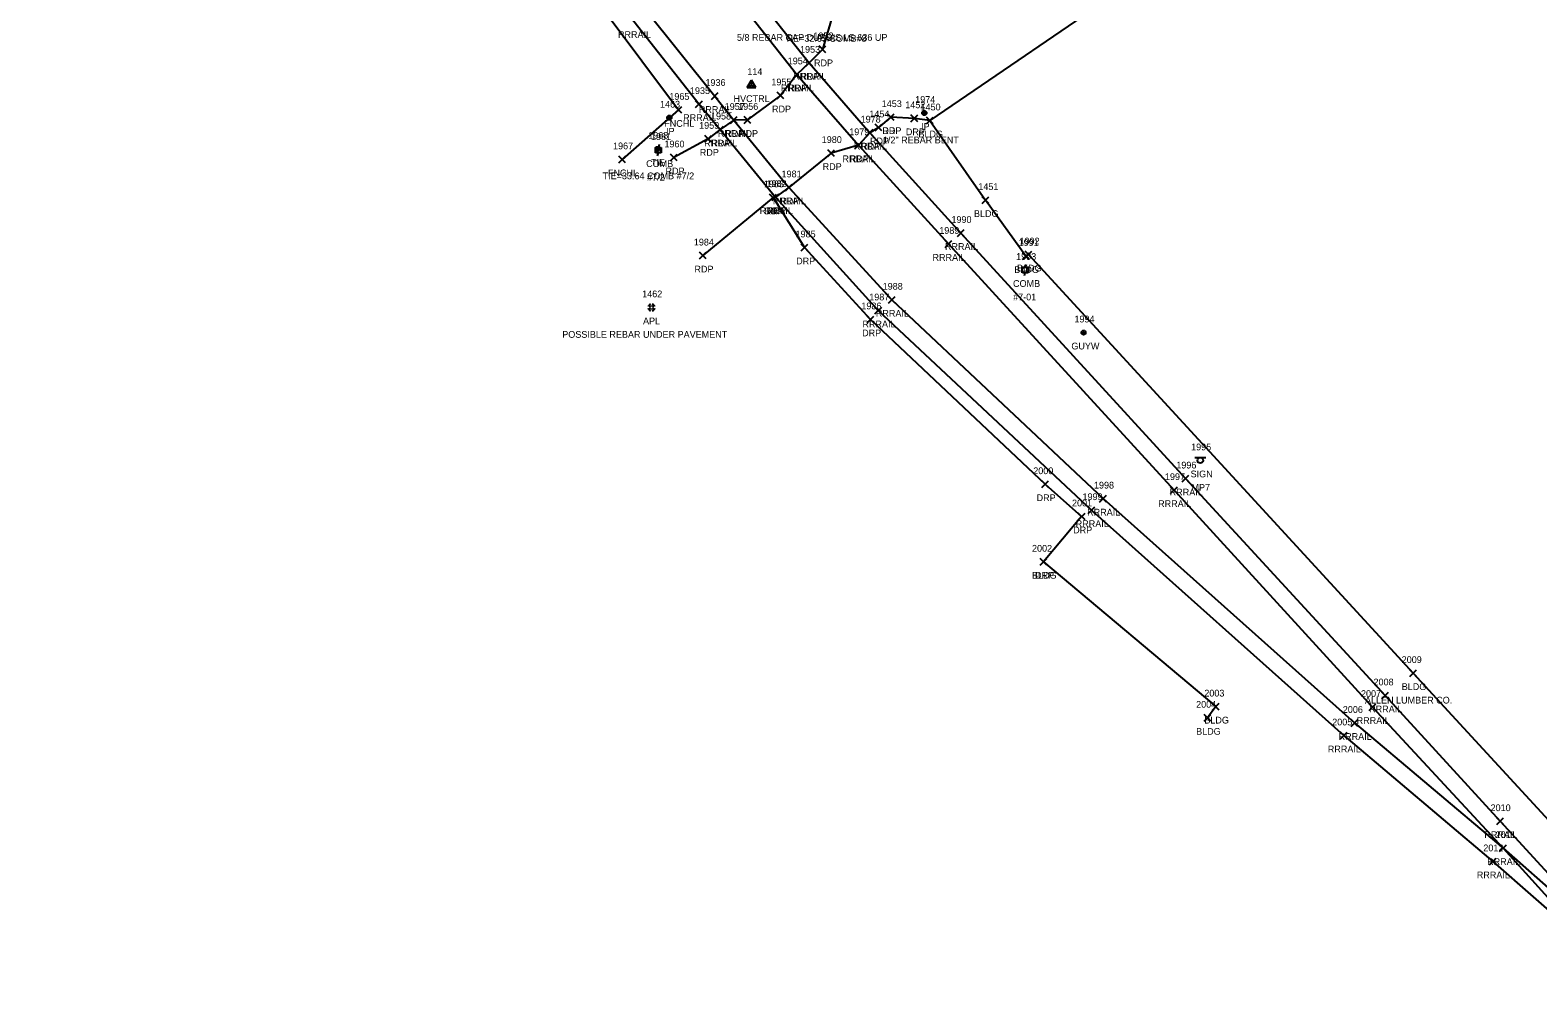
# Model space of a CAD drawing. Extents: x 1635588 to 1637550, y 621583 to 623638.
# Drawn here: x 1636590.6 to 1637037.4, y 621876.2 to 622165 of the extents above; entities that cross this region are included whole.
import ezdxf

# ---------------------------------------------------------------- set-up
doc = ezdxf.new("R2010")
doc.units = 0
for name, color, linetype in [('C_A', 7, 'Continuous'), ('C_C', 7, 'Continuous'), ('C_I', 7, 'Continuous'), ('CBP', 7, 'Continuous'), ('CPSM', 7, 'Continuous'), ('Default', 7, 'Continuous'), ('L_A', 7, 'Continuous'), ('L_C', 7, 'Continuous'), ('L_I', 7, 'Continuous'), ('L_TIC', 7, 'Continuous'), ('LBC', 7, 'Continuous'), ('LFNC', 7, 'Continuous'), ('M_A', 7, 'Continuous'), ('M_C', 7, 'Continuous'), ('M_I', 7, 'Continuous'), ('MPIR', 7, 'Continuous'), ('P_A', 7, 'Continuous'), ('P_I', 7, 'Continuous'), ('P_TIC', 7, 'Continuous'), ('PET', 7, 'Continuous'), ('R_A', 7, 'Continuous'), ('R_I', 7, 'Continuous'), ('R_TIC', 7, 'Continuous'), ('RDP', 7, 'Continuous'), ('RR', 7, 'Continuous'), ('S_A', 7, 'Continuous'), ('S_C', 7, 'Continuous'), ('S_I', 7, 'Continuous'), ('SSGN', 7, 'Continuous'), ('U_A', 7, 'Continuous'), ('U_C', 7, 'Continuous'), ('U_I', 7, 'Continuous'), ('UP', 7, 'Continuous'), ('UPGW', 7, 'Continuous')]:
    doc.layers.add(name, color=color, linetype=linetype)

msp = doc.modelspace()

# ---------------------------------------------------------------- linework, layer by layer
at = {"layer": 'CBP'}
for radius in [0.625, 0.0833]:
    msp.add_circle((1636776.52, 622129.85), radius, dxfattribs=at)
at = {"layer": 'CPSM'}
for p, q in [((1636803.12, 622148), (1636804.37, 622150.17)), ((1636805.62, 622148), (1636804.37, 622150.17)), ((1636804.37, 622148.73), (1636804.37, 622150.17)), ((1636803.12, 622148), (1636804.37, 622148.73)), ((1636803.12, 622148), (1636805.62, 622148)), ((1636804.37, 622148.73), (1636804.37, 622148.73)), ((1636804.37, 622148.73), (1636805.62, 622148))]:
    msp.add_line(p, q, dxfattribs=at)
at = {"layer": 'Default'}
for p, q in [((1636774.09, 622083.5), (1636774.45, 622083.15)), ((1636774.09, 622082.23), (1636774.45, 622082.58)), ((1636774.13, 622082.87), (1636774.43, 622082.87)), ((1636774.73, 622083.17), (1636774.73, 622083.47)), ((1636774.73, 622082.27), (1636774.73, 622082.57)), ((1636775.01, 622083.15), (1636775.37, 622083.5)), ((1636775.01, 622082.58), (1636775.37, 622082.23)), ((1636775.03, 622082.87), (1636775.33, 622082.87))]:
    msp.add_line(p, q, dxfattribs=at)
for start, end in [(105, 165), (195, 255), (15, 75), (285, 345)]:
    msp.add_arc((1636774.73, 622082.87), 1, start, end, dxfattribs=at)
at = {"layer": 'L_TIC'}
for points in [[(1636781.77, 622140.38), (1636783.77, 622142.38)], [(1636783.77, 622140.38), (1636781.77, 622142.38)], [(1636856.25, 622137.25), (1636858.25, 622139.25)], [(1636858.25, 622137.25), (1636856.25, 622139.25)], [(1636765.09, 622125.73), (1636767.09, 622127.73)], [(1636767.09, 622125.73), (1636765.09, 622127.73)], [(1636872.71, 622113.67), (1636874.71, 622115.67)], [(1636874.71, 622113.67), (1636872.71, 622115.67)], [(1636884.66, 622097.09), (1636886.66, 622099.09)], [(1636886.66, 622097.09), (1636884.66, 622099.09)], [(1636885.49, 622097.53), (1636887.49, 622099.53)], [(1636887.49, 622097.53), (1636885.49, 622099.53)], [(1636889.91, 622006.5), (1636891.91, 622008.5)], [(1636891.91, 622006.5), (1636889.91, 622008.5)], [(1636999.47, 621973.51), (1637001.47, 621975.51)], [(1637001.47, 621973.51), (1636999.47, 621975.51)], [(1636938.54, 621960.26), (1636940.54, 621962.26)], [(1636940.54, 621960.26), (1636938.54, 621962.26)], [(1636940.98, 621963.59), (1636942.98, 621965.59)], [(1636942.98, 621963.59), (1636940.98, 621965.59)]]:
    msp.add_lwpolyline(points, dxfattribs=at)
at = {"layer": 'LBC'}
for points in [[(1636917.78, 622179.59), (1636857.25, 622138.25), (1636873.71, 622114.67)], [(1636885.66, 622098.09), (1636873.71, 622114.67)], [(1636885.66, 622098.09), (1636886.49, 622098.53), (1637000.47, 621974.51), (1637086.58, 621881), (1637094.62, 621887.96), (1637096.59, 621890.08)], [(1636890.91, 622007.5), (1636941.98, 621964.59), (1636939.54, 621961.26)]]:
    msp.add_lwpolyline(points, dxfattribs=at)
at = {"layer": 'LFNC'}
msp.add_lwpolyline([(1636739.42, 622178.03), (1636750.15, 622185.05), (1636782.77, 622141.38), (1636766.09, 622126.73)], dxfattribs=at)
at = {"layer": 'MPIR'}
for points in [[(1636855.58, 622140.82), (1636855.3, 622140.32), (1636855.87, 622140.32)], [(1636780.01, 622139.41), (1636779.72, 622138.91), (1636780.3, 622138.91)]]:
    msp.add_lwpolyline(points, close=True, dxfattribs=at)
for centre in [(1636855.58, 622140.48), (1636780.01, 622139.08)]:
    msp.add_circle(centre, 0.667, dxfattribs=at)
at = {"layer": 'P_TIC'}
for points in [[(1636824.41, 622158.33), (1636826.41, 622160.33)], [(1636826.41, 622158.33), (1636824.41, 622160.33)], [(1636820.45, 622154.32), (1636822.45, 622156.32)], [(1636822.45, 622154.32), (1636820.45, 622156.32)], [(1636816.8, 622150.9), (1636818.8, 622152.9)], [(1636818.8, 622150.9), (1636816.8, 622152.9)], [(1636811.96, 622144.66), (1636813.96, 622146.66)], [(1636813.96, 622144.66), (1636811.96, 622146.66)], [(1636794.06, 622134.55), (1636796.06, 622136.55)], [(1636796.06, 622134.55), (1636794.06, 622136.55)], [(1636798.12, 622137.4), (1636800.12, 622139.4)], [(1636800.12, 622137.4), (1636798.12, 622139.4)], [(1636802.18, 622137.41), (1636804.18, 622139.41)], [(1636804.18, 622137.41), (1636802.18, 622139.41)], [(1636840.98, 622135.18), (1636842.98, 622137.18)], [(1636842.98, 622135.18), (1636840.98, 622137.18)], [(1636844.66, 622138.23), (1636846.66, 622140.23)], [(1636846.66, 622138.23), (1636844.66, 622140.23)], [(1636790.56, 622131.8), (1636792.56, 622133.8)], [(1636792.56, 622131.8), (1636790.56, 622133.8)], [(1636835.04, 622129.9), (1636837.04, 622131.9)], [(1636837.04, 622129.9), (1636835.04, 622131.9)], [(1636838.4, 622133.64), (1636840.4, 622135.64)], [(1636840.4, 622133.64), (1636838.4, 622135.64)], [(1636780.4, 622126.29), (1636782.4, 622128.29)], [(1636782.4, 622126.29), (1636780.4, 622128.29)], [(1636826.97, 622127.6), (1636828.97, 622129.6)], [(1636828.97, 622127.6), (1636826.97, 622129.6)], [(1636814.41, 622117.42), (1636816.41, 622119.42)], [(1636816.41, 622117.42), (1636814.41, 622119.42)], [(1636809.75, 622114.47), (1636811.75, 622116.47)], [(1636811.75, 622114.47), (1636809.75, 622116.47)], [(1636810.52, 622114.54), (1636812.52, 622116.54)], [(1636812.52, 622114.54), (1636810.52, 622116.54)], [(1636788.98, 622097.22), (1636790.98, 622099.22)], [(1636790.98, 622097.22), (1636788.98, 622099.22)]]:
    msp.add_lwpolyline(points, dxfattribs=at)
at = {"layer": 'PET'}
for points in [[(1636828.72, 622170.37), (1636825.41, 622159.33)], [(1636825.41, 622159.33), (1636821.45, 622155.32), (1636817.8, 622151.9), (1636812.96, 622145.66), (1636803.18, 622138.41), (1636799.12, 622138.4), (1636795.06, 622135.55), (1636791.56, 622132.8), (1636781.4, 622127.29)], [(1636841.98, 622136.18), (1636839.4, 622134.64)], [(1636845.66, 622139.23), (1636841.98, 622136.18)], [(1636839.4, 622134.64), (1636836.04, 622130.9), (1636827.97, 622128.6), (1636815.41, 622118.42), (1636811.52, 622115.54), (1636810.75, 622115.47), (1636789.98, 622098.22)]]:
    msp.add_lwpolyline(points, dxfattribs=at)
at = {"layer": 'R_TIC'}
for points in [[(1636820.45, 622154.32), (1636822.45, 622156.32)], [(1636822.45, 622154.32), (1636820.45, 622156.32)], [(1636816.8, 622150.9), (1636818.8, 622152.9)], [(1636818.8, 622150.9), (1636816.8, 622152.9)], [(1636792.48, 622144.5), (1636794.48, 622146.5)], [(1636794.48, 622144.5), (1636792.48, 622146.5)], [(1636787.83, 622142.09), (1636789.83, 622144.09)], [(1636789.83, 622142.09), (1636787.83, 622144.09)], [(1636794.06, 622134.55), (1636796.06, 622136.55)], [(1636796.06, 622134.55), (1636794.06, 622136.55)], [(1636798.12, 622137.4), (1636800.12, 622139.4)], [(1636800.12, 622137.4), (1636798.12, 622139.4)], [(1636844.66, 622138.23), (1636846.66, 622140.23)], [(1636846.66, 622138.23), (1636844.66, 622140.23)], [(1636851.64, 622137.89), (1636853.64, 622139.89)], [(1636853.64, 622137.89), (1636851.64, 622139.89)], [(1636835.04, 622129.9), (1636837.04, 622131.9)], [(1636837.04, 622129.9), (1636835.04, 622131.9)], [(1636838.4, 622133.64), (1636840.4, 622135.64)], [(1636840.4, 622133.64), (1636838.4, 622135.64)], [(1636814.41, 622117.42), (1636816.41, 622119.42)], [(1636816.41, 622117.42), (1636814.41, 622119.42)], [(1636809.75, 622114.47), (1636811.75, 622116.47)], [(1636811.75, 622114.47), (1636809.75, 622116.47)], [(1636810.52, 622114.54), (1636812.52, 622116.54)], [(1636812.52, 622114.54), (1636810.52, 622116.54)], [(1636865.41, 622103.91), (1636867.41, 622105.91)], [(1636867.41, 622103.91), (1636865.41, 622105.91)], [(1636819.12, 622099.62), (1636821.12, 622101.62)], [(1636821.12, 622099.62), (1636819.12, 622101.62)], [(1636861.72, 622100.67), (1636863.72, 622102.67)], [(1636863.72, 622100.67), (1636861.72, 622102.67)], [(1636840.96, 622080.95), (1636842.96, 622082.95)], [(1636842.96, 622080.95), (1636840.96, 622082.95)], [(1636844.94, 622084.12), (1636846.94, 622086.12)], [(1636846.94, 622084.12), (1636844.94, 622086.12)], [(1636838.67, 622078.31), (1636840.67, 622080.31)], [(1636840.67, 622078.31), (1636838.67, 622080.31)], [(1636890.38, 622029.47), (1636892.38, 622031.47)], [(1636892.38, 622029.47), (1636890.38, 622031.47)], [(1636928.58, 622027.72), (1636930.58, 622029.72)], [(1636930.58, 622027.72), (1636928.58, 622029.72)], [(1636932.01, 622031.15), (1636934.01, 622033.15)], [(1636934.01, 622031.15), (1636932.01, 622033.15)], [(1636907.55, 622025.21), (1636909.55, 622027.21)], [(1636909.55, 622025.21), (1636907.55, 622027.21)], [(1636901.21, 622019.92), (1636903.21, 622021.92)], [(1636903.21, 622019.92), (1636901.21, 622021.92)], [(1636904.16, 622021.78), (1636906.16, 622023.78)], [(1636906.16, 622021.78), (1636904.16, 622023.78)], [(1636889.91, 622006.5), (1636891.91, 622008.5)], [(1636891.91, 622006.5), (1636889.91, 622008.5)], [(1636991.12, 621966.88), (1636993.12, 621968.88)], [(1636993.12, 621966.88), (1636991.12, 621968.88)], [(1636987.41, 621963.46), (1636989.41, 621965.46)], [(1636989.41, 621963.46), (1636987.41, 621965.46)], [(1636982.07, 621958.74), (1636984.07, 621960.74)], [(1636984.07, 621958.74), (1636982.07, 621960.74)], [(1636978.87, 621955.02), (1636980.87, 621957.02)], [(1636980.87, 621955.02), (1636978.87, 621957.02)], [(1637025.25, 621929.62), (1637027.25, 621931.62)], [(1637027.25, 621929.62), (1637025.25, 621931.62)], [(1637026.08, 621921.66), (1637028.08, 621923.66)], [(1637028.08, 621921.66), (1637026.08, 621923.66)], [(1637026.08, 621921.66), (1637028.08, 621923.66)], [(1637028.08, 621921.66), (1637026.08, 621923.66)], [(1637023.02, 621917.73), (1637025.02, 621919.73)], [(1637025.02, 621917.73), (1637023.02, 621919.73)]]:
    msp.add_lwpolyline(points, dxfattribs=at)
at = {"layer": 'RDP'}
for points in [[(1636852.64, 622138.89), (1636845.66, 622139.23)], [(1636857.25, 622138.25), (1636852.64, 622138.89)], [(1636810.75, 622115.47), (1636820.12, 622100.62), (1636839.67, 622079.31), (1636891.38, 622030.47), (1636902.21, 622020.92), (1636890.91, 622007.5)]]:
    msp.add_lwpolyline(points, dxfattribs=at)
at = {"layer": 'RR'}
for points in [[(1636590.62, 622643.06), (1636603.96, 622594.72), (1636620.27, 622536.36), (1636632.07, 622498.45), (1636643.29, 622466.78), (1636655.39, 622436.56), (1636668.93, 622406.09), (1636689.56, 622363.97), (1636710.33, 622322.06), (1636729.55, 622284.99), (1636743.57, 622259.26), (1636761.55, 622228.91), (1636778.55, 622203.2), (1636800.49, 622173.78), (1636817.8, 622151.9), (1636836.04, 622130.9), (1636862.72, 622101.67), (1636929.58, 622028.72), (1636988.41, 621964.46), (1637027.08, 621922.66), (1637047.82, 621899.75)], [(1636595.36, 622644.51), (1636608.64, 622596.11), (1636625.13, 622537.69), (1636636.8, 622500.24), (1636648.02, 622468.59), (1636659.97, 622438.55), (1636673.52, 622408.34), (1636693.85, 622366.08), (1636714.7, 622324.39), (1636733.88, 622287.48), (1636747.97, 622261.4), (1636765.42, 622232.02), (1636782.99, 622205.69), (1636804, 622177.32), (1636821.45, 622155.32), (1636839.4, 622134.64), (1636866.41, 622104.91), (1636933.01, 622032.15), (1636992.12, 621967.88), (1637026.25, 621930.62), (1637051.37, 621903.17)], [(1636647.57, 622303.46), (1636681.53, 622274.07), (1636698.35, 622258.6), (1636736.07, 622216.66), (1636772.81, 622171.31), (1636793.48, 622145.5), (1636799.12, 622138.4), (1636815.41, 622118.42), (1636845.94, 622085.12), (1636908.55, 622026.21), (1636983.07, 621959.74), (1637027.08, 621922.66), (1637050.39, 621902.14), (1637074.4, 621880.01)], [(1636645.23, 622298.69), (1636678.25, 622270.68), (1636695.49, 622253.83), (1636732.46, 622213.3), (1636769.51, 622167.71), (1636788.83, 622143.09), (1636795.06, 622135.55), (1636811.52, 622115.54), (1636841.96, 622081.95), (1636905.16, 622022.78), (1636979.87, 621956.02), (1637024.02, 621918.73), (1637048, 621897.73), (1637071.19, 621876.23)]]:
    msp.add_lwpolyline(points, dxfattribs=at)
at = {"layer": 'SSGN'}
for p, q in [((1636935.71, 622038.38), (1636939.05, 622038.38)), ((1636937.36, 622037.55), (1636937.36, 622037.55))]:
    msp.add_line(p, q, dxfattribs=at)
msp.add_circle((1636937.36, 622037.55), 0.833, dxfattribs=at)
at = {"layer": 'UP'}
for p, q in [((1636775.94, 622128.63), (1636775.94, 622130.29)), ((1636775.94, 622130.29), (1636777.61, 622130.29)), ((1636777.61, 622128.63), (1636775.94, 622128.63)), ((1636776.53, 622127.79), (1636776.78, 622128.63)), ((1636777.03, 622131.13), (1636776.78, 622130.29)), ((1636776.78, 622129.46), (1636776.78, 622129.46)), ((1636777.61, 622130.29), (1636777.61, 622128.63)), ((1636884.66, 622093.12), (1636884.66, 622094.79)), ((1636884.66, 622094.79), (1636886.33, 622094.79)), ((1636886.33, 622093.12), (1636884.66, 622093.12)), ((1636885.25, 622092.29), (1636885.5, 622093.12)), ((1636885.75, 622095.62), (1636885.5, 622094.79)), ((1636885.5, 622093.95), (1636885.5, 622093.95)), ((1636886.33, 622094.79), (1636886.33, 622093.12))]:
    msp.add_line(p, q, dxfattribs=at)
for centre in [(1636776.78, 622129.46), (1636885.5, 622093.95)]:
    msp.add_circle(centre, 0.833, dxfattribs=at)
at = {"layer": 'UPGW'}
for radius in [0.625, 0.0833]:
    msp.add_circle((1636902.77, 622075.42), radius, dxfattribs=at)

# ---------------------------------------------------------------- texts
at = {"layer": 'C_A'}
for s, p in [('HVCTRL', (1636799.06, 622143.73)), ('TIE', (1636774.6, 622124.85))]:
    msp.add_text(s, height=2, dxfattribs=at).set_placement(p)
at = {"layer": 'C_C'}
for s, p in [('TIE=32.05 COMB#8', (1636814.33, 622161.58)), ('TIE=33.64 COMB #7/2', (1636760.26, 622120.85))]:
    msp.add_text(s, height=2, dxfattribs=at).set_placement(p)
at = {"layer": 'C_I'}
for s, p in [('114', (1636803.14, 622151.73)), ('1968', (1636773.78, 622132.85))]:
    msp.add_text(s, height=2, dxfattribs=at).set_placement(p)
at = {"layer": 'L_A'}
for s, p in [('FNCHL', (1636778.52, 622136.38)), ('BLDG', (1636853.84, 622133.25)), ('FNCHL', (1636761.84, 622121.73)), ('BLDG', (1636870.3, 622109.67)), ('BLDG', (1636882.25, 622093.09)), ('BLDG', (1636883.08, 622093.53)), ('BLDG', (1636887.5, 622002.5)), ('BLDG', (1636997.06, 621969.51)), ('BLDG', (1636936.13, 621956.26)), ('BLDG', (1636938.57, 621959.59))]:
    msp.add_text(s, height=2, dxfattribs=at).set_placement(p)
at = {"layer": 'L_C'}
msp.add_text('ALLEN LUMBER CO.', height=2, dxfattribs=at).set_placement((1636986.17, 621965.51))
at = {"layer": 'L_I'}
for s, p in [('1965', (1636780.03, 622144.38)), ('1450', (1636854.47, 622141.25)), ('1967', (1636763.35, 622129.73)), ('1451', (1636871.59, 622117.67)), ('1991', (1636883.53, 622101.09)), ('1992', (1636883.8, 622101.53)), ('2002', (1636887.5, 622010.5)), ('2009', (1636997.05, 621977.51)), ('2003', (1636938.56, 621967.59)), ('2004', (1636936.13, 621964.26))]:
    msp.add_text(s, height=2, dxfattribs=at).set_placement(p)
at = {"layer": 'M_A'}
for s, p in [('IP', (1636854.63, 622135.48)), ('IP', (1636779.06, 622134.08)), ('APL', (1636772.24, 622077.87))]:
    msp.add_text(s, height=2, dxfattribs=at).set_placement(p)
at = {"layer": 'M_C'}
for s, p in [('5/8 REBAR CAP DUBOIS LS 636 UP', (1636800.06, 622161.86)), ('1/2" REBAR BENT', (1636843.31, 622131.48)), ('POSSIBLE REBAR UNDER PAVEMENT', (1636748.3, 622073.87))]:
    msp.add_text(s, height=2, dxfattribs=at).set_placement(p)
at = {"layer": 'M_I'}
for s, p in [('1974', (1636852.89, 622143.48)), ('1463', (1636777.27, 622142.08)), ('1462', (1636771.99, 622085.87))]:
    msp.add_text(s, height=2, dxfattribs=at).set_placement(p)
at = {"layer": 'P_A'}
for p in [(1636822.9, 622154.33), (1636818.94, 622150.32), (1636815.29, 622146.9), (1636810.45, 622140.66), (1636843.15, 622134.23), (1636792.55, 622130.55), (1636796.61, 622133.4), (1636800.67, 622133.41), (1636839.47, 622131.18), (1636789.05, 622127.8), (1636833.53, 622125.9), (1636836.89, 622129.64), (1636778.89, 622122.29), (1636825.46, 622123.6), (1636812.9, 622113.42), (1636808.23, 622110.47), (1636809.01, 622110.54), (1636787.47, 622093.22)]:
    msp.add_text('RDP', height=2, dxfattribs=at).set_placement(p)
at = {"layer": 'P_I'}
for s, p in [('1952', (1636822.72, 622162.33)), ('1953', (1636818.76, 622158.32)), ('1954', (1636815.11, 622154.9)), ('1955', (1636810.26, 622148.66)), ('1957', (1636796.43, 622141.4)), ('1956', (1636800.43, 622141.41)), ('1454', (1636839.29, 622139.18)), ('1453', (1636842.97, 622142.23)), ('1959', (1636788.86, 622135.8)), ('1958', (1636792.37, 622138.55)), ('1978', (1636836.71, 622137.64)), ('1960', (1636778.58, 622130.29)), ('1980', (1636825.19, 622131.6)), ('1979', (1636833.34, 622133.9)), ('1981', (1636813.28, 622121.42)), ('1983', (1636808.05, 622118.47)), ('1982', (1636808.83, 622118.54)), ('1984', (1636787.29, 622101.22))]:
    msp.add_text(s, height=2, dxfattribs=at).set_placement(p)
at = {"layer": 'R_A'}
for s, p in [('RRRAIL', (1636764.8, 622162.71)), ('RRRAIL', (1636816.74, 622150.32)), ('RRRAIL', (1636813.09, 622146.9)), ('RRRAIL', (1636788.77, 622140.5)), ('RRRAIL', (1636784.12, 622138.09)), ('DRP', (1636843.15, 622134.23)), ('RRRAIL', (1636790.35, 622130.55)), ('RRRAIL', (1636794.41, 622133.4)), ('DRP', (1636850.12, 622133.89)), ('RRRAIL', (1636831.34, 622125.9)), ('RRRAIL', (1636834.69, 622129.64)), ('RRRAIL', (1636810.7, 622113.42)), ('RRRAIL', (1636806.81, 622110.54)), ('DRP', (1636808.23, 622110.47)), ('RRRAIL', (1636861.7, 622099.91)), ('DRP', (1636817.61, 622095.62)), ('RRRAIL', (1636858.01, 622096.67)), ('RRRAIL', (1636837.25, 622076.95)), ('RRRAIL', (1636841.23, 622080.12)), ('DRP', (1636837.16, 622074.31)), ('RRRAIL', (1636928.3, 622027.15)), ('DRP', (1636888.86, 622025.47)), ('RRRAIL', (1636924.87, 622023.72)), ('RRRAIL', (1636903.84, 622021.21)), ('DRP', (1636899.7, 622015.92)), ('RRRAIL', (1636900.45, 622017.78)), ('DRP', (1636888.4, 622002.5)), ('RRRAIL', (1636987.41, 621962.88)), ('RRRAIL', (1636983.7, 621959.46)), ('RRRAIL', (1636975.16, 621951.02)), ('RRRAIL', (1636978.36, 621954.74)), ('RRRAIL', (1637021.54, 621925.62)), ('RRRAIL', (1637022.37, 621917.66)), ('RRRAIL', (1637022.37, 621917.66)), ('RRRAIL', (1637019.31, 621913.73))]:
    msp.add_text(s, height=2, dxfattribs=at).set_placement(p)
at = {"layer": 'R_I'}
for s, p in [('1953', (1636818.76, 622158.32)), ('1954', (1636815.11, 622154.9)), ('1936', (1636790.73, 622148.5)), ('1935', (1636786.13, 622146.09)), ('1957', (1636796.43, 622141.4)), ('1453', (1636842.97, 622142.23)), ('1452', (1636849.94, 622141.89)), ('1958', (1636792.37, 622138.55)), ('1978', (1636836.71, 622137.64)), ('1979', (1636833.34, 622133.9)), ('1981', (1636813.28, 622121.42)), ('1983', (1636808.05, 622118.47)), ('1982', (1636808.83, 622118.54)), ('1990', (1636863.63, 622107.91)), ('1985', (1636817.43, 622103.62)), ('1989', (1636860.02, 622104.67)), ('1988', (1636843.25, 622088.12)), ('1986', (1636836.93, 622082.31)), ('1987', (1636839.27, 622084.95)), ('2000', (1636887.87, 622033.47)), ('1997', (1636926.89, 622031.72)), ('1996', (1636930.26, 622035.15)), ('1998', (1636905.86, 622029.21)), ('2001', (1636899.36, 622023.92)), ('1999', (1636902.46, 622025.78)), ('2002', (1636887.5, 622010.5)), ('2008', (1636988.7, 621970.88)), ('2007', (1636984.99, 621967.46)), ('2006', (1636979.6, 621962.74)), ('2005', (1636976.46, 621959.02)), ('2010', (1637023.39, 621933.62)), ('2011', (1637024.87, 621925.66)), ('2011', (1637024.87, 621925.66)), ('2012', (1637021.24, 621921.73))]:
    msp.add_text(s, height=2, dxfattribs=at).set_placement(p)
at = {"layer": 'S_A'}
msp.add_text('SIGN', height=2, dxfattribs=at).set_placement((1636934.5, 622032.53))
at = {"layer": 'S_C'}
msp.add_text('MP7', height=2, dxfattribs=at).set_placement((1636934.76, 622028.53))
at = {"layer": 'S_I'}
msp.add_text('1995', height=2, dxfattribs=at).set_placement((1636934.65, 622040.53))
at = {"layer": 'U_A'}
for s, p in [('COMB', (1636773.16, 622124.46)), ('COMB', (1636881.88, 622088.95)), ('GUYW', (1636899.16, 622070.42))]:
    msp.add_text(s, height=2, dxfattribs=at).set_placement(p)
at = {"layer": 'U_C'}
for s, p in [('#8', (1636826.17, 622161.62)), ('#7/2', (1636773.44, 622120.46)), ('#7-01', (1636881.91, 622084.95))]:
    msp.add_text(s, height=2, dxfattribs=at).set_placement(p)
at = {"layer": 'U_I'}
for s, p in [('1961', (1636774.6, 622132.46)), ('1993', (1636882.8, 622096.95)), ('1994', (1636900.08, 622078.42))]:
    msp.add_text(s, height=2, dxfattribs=at).set_placement(p)

doc.saveas('drawing.dxf')
